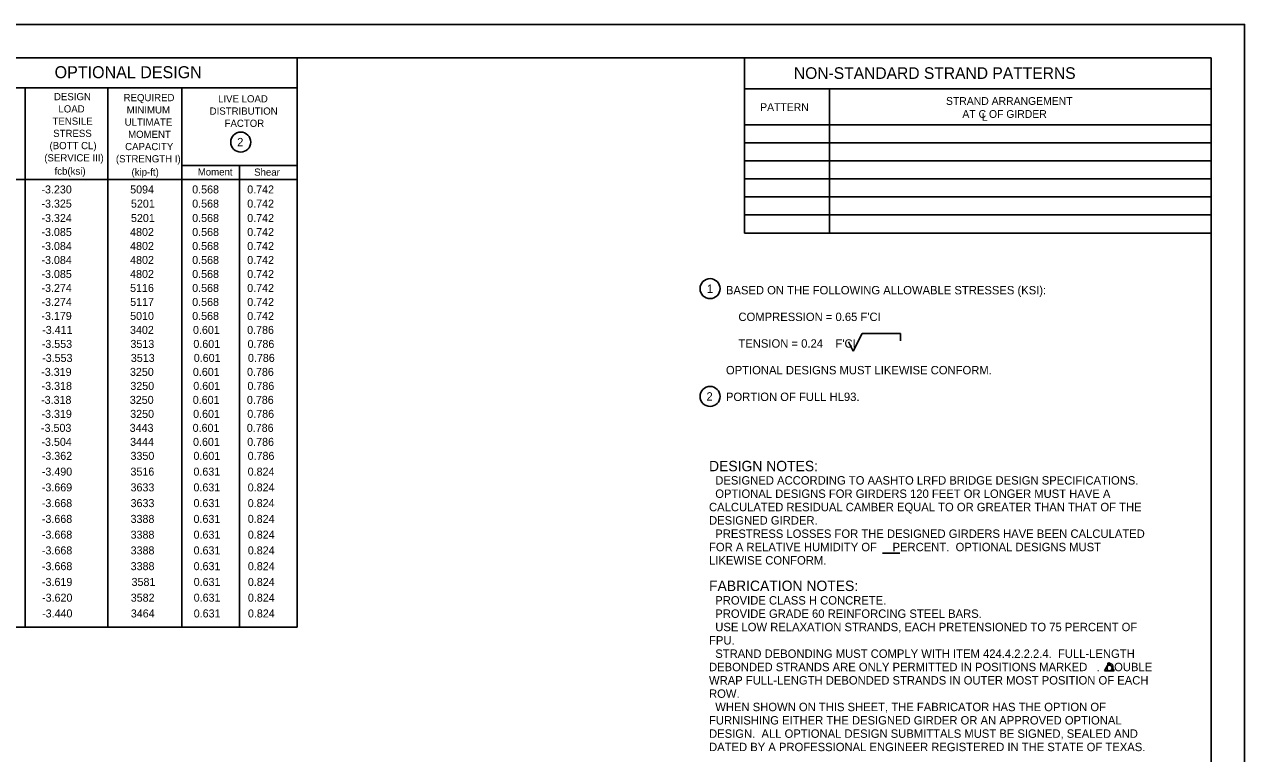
# Model space of a CAD drawing. Extents: x 998.6 to 1033.3, y 1000 to 1011.
# Drawn here: x 1007.85 to 1017, y 1005.53 to 1011 of the extents above; entities that cross this region are included whole.
import ezdxf

# ---------------------------------------------------------------- set-up
doc = ezdxf.new("R2010")
doc.units = 0
for name, color, linetype in [('D_BATCH_PLOT', 7, 'Continuous'), ('D_SHEET', 7, 'Continuous'), ('Working Level 1', 7, 'Continuous')]:
    doc.layers.add(name, color=color, linetype=linetype)

msp = doc.modelspace()

# ---------------------------------------------------------------- linework, layer by layer
at = {"layer": 'D_BATCH_PLOT'}
msp.add_lwpolyline([(1000, 1000), (1017, 1000), (1017, 1011), (1000, 1011)], close=True, dxfattribs=at)
at = {"layer": 'D_SHEET'}
for p, q in [((1000, 1011), (1017, 1011)), ((1017, 1000), (1017, 1011)), ((1001, 1010.75), (1016.75, 1010.75)), ((1016.75, 1000.25), (1016.75, 1010.75))]:
    msp.add_line(p, q, dxfattribs=at)
at = {"layer": 'Working Level 1'}
for p, q in [((1009.8951, 1010.75), (1009.8951, 1006.477)), ((1013.25, 1009.4346), (1013.25, 1010.75)), ((1013.25, 1010.75), (1016.75, 1010.75)), ((1016.75, 1009.4346), (1016.75, 1010.75)), ((1007.2976, 1010.5232), (1009.8951, 1010.5232)), ((1007.8546, 1010.5232), (1007.8546, 1006.477)), ((1008.4741, 1010.5232), (1008.4741, 1006.477)), ((1009.0311, 1010.5232), (1009.0311, 1006.477)), ((1013.25, 1010.5171), (1016.75, 1010.5171)), ((1013.8867, 1009.4346), (1013.8867, 1010.5166)), ((1013.25, 1010.2466), (1016.75, 1010.2466)), ((1013.25, 1010.1116), (1016.75, 1010.1116)), ((1009.0311, 1009.9417), (1009.8951, 1009.9417)), ((1009.4631, 1009.9417), (1009.4631, 1006.477)), ((1013.25, 1009.9762), (1016.75, 1009.9762)), ((1007.2976, 1009.8354), (1009.8951, 1009.8354)), ((1013.25, 1009.8408), (1016.75, 1009.8408)), ((1013.25, 1009.7054), (1016.75, 1009.7054)), ((1013.25, 1009.57), (1016.75, 1009.57)), ((1013.25, 1009.4346), (1016.75, 1009.4346)), ((1014.0652, 1008.5479), (1014.1325, 1008.6804)), ((1014.1325, 1008.6804), (1014.419, 1008.6804)), ((1014.419, 1008.626), (1014.419, 1008.6804)), ((1014.0299, 1008.6184), (1014.0652, 1008.5479)), ((1014.2851, 1007.0327), (1014.4142, 1007.0327)), ((1001, 1006.477), (1009.8951, 1006.477)), ((1015.9854, 1006.213), (1015.9493, 1006.1505)), ((1016.0215, 1006.1505), (1015.9854, 1006.213)), ((1015.9493, 1006.1505), (1016.0215, 1006.1505))]:
    msp.add_line(p, q, dxfattribs=at)
for centre, radius in [((1009.4717, 1010.1168), 0.075), ((1012.9913, 1009.0173), 0.075), ((1012.9913, 1008.2086), 0.075), ((1015.9854, 1006.1713), 0.0208)]:
    msp.add_circle(centre, radius, dxfattribs=at)

# ---------------------------------------------------------------- texts
for s, height, p in [('OPTIONAL DESIGN', 0.09, (1008.0761, 1010.5964)), ('NON-STANDARD STRAND PATTERNS', 0.0875, (1013.62, 1010.5909)), ('DESIGN', 0.054, (1008.0714, 1010.431)), ('REQUIRED', 0.054, (1008.5934, 1010.4237)), ('LIVE LOAD', 0.054, (1009.3018, 1010.4147)), ('PATTERN', 0.05833, (1013.3673, 1010.35)), ('STRAND ARRANGEMENT', 0.058332, (1014.7608, 1010.3962)), ('LOAD', 0.054, (1008.1045, 1010.3392)), ('MINIMUM', 0.054, (1008.6166, 1010.3319)), ('DISTRIBUTION', 0.054, (1009.239, 1010.3229)), ('AT C OF GIRDER', 0.058332, (1014.8837, 1010.2987)), ('L', 0.0583, (1015.0294, 1010.2769)), ('TENSILE', 0.054, (1008.0603, 1010.2474)), ('ULTIMATE', 0.054, (1008.6013, 1010.2401)), ('FACTOR', 0.054, (1009.3507, 1010.2311)), ('STRESS', 0.054, (1008.0654, 1010.1556)), ('MOMENT', 0.054, (1008.627, 1010.1483)), ('2', 0.063, (1009.4447, 1010.0852)), ('(BOTT CL)', 0.054, (1008.0378, 1010.0638)), ('CAPACITY', 0.054, (1008.6049, 1010.0565)), ('(SERVICE III)', 0.054, (1007.9987, 1009.972)), ('(STRENGTH I)', 0.054, (1008.5357, 1009.9647)), ('fcb(ksi)', 0.054, (1008.0758, 1009.8723)), ('(kip-ft)', 0.054, (1008.6527, 1009.8651)), ('Moment', 0.054, (1009.1495, 1009.8663)), ('Shear', 0.054, (1009.5724, 1009.8646)), ('-3.230', 0.06, (1007.9773, 1009.7317)), ('5094', 0.06, (1008.6427, 1009.7317)), ('0.568', 0.06, (1009.1079, 1009.7317)), ('0.742', 0.06, (1009.5206, 1009.7317)), ('-3.325', 0.06, (1007.9773, 1009.6254)), ('5201', 0.06, (1008.6488, 1009.6254)), ('0.568', 0.06, (1009.1079, 1009.6254)), ('0.742', 0.06, (1009.5206, 1009.6254)), ('-3.324', 0.06, (1007.9775, 1009.5174)), ('5201', 0.06, (1008.6488, 1009.5174)), ('0.568', 0.06, (1009.1079, 1009.5174)), ('0.742', 0.06, (1009.5206, 1009.5174)), ('-3.085', 0.06, (1007.9773, 1009.4124)), ('4802', 0.06, (1008.6422, 1009.4124)), ('0.568', 0.06, (1009.1079, 1009.4124)), ('0.742', 0.06, (1009.5206, 1009.4124)), ('-3.084', 0.06, (1007.9775, 1009.3075)), ('-3.084', 0.06, (1007.9775, 1009.3075)), ('4802', 0.06, (1008.6422, 1009.3075)), ('4802', 0.06, (1008.6422, 1009.3075)), ('0.568', 0.06, (1009.1079, 1009.3075)), ('0.568', 0.06, (1009.1079, 1009.3075)), ('0.742', 0.06, (1009.5206, 1009.3075)), ('0.742', 0.06, (1009.5206, 1009.3075)), ('-3.084', 0.06, (1007.9775, 1009.2025)), ('4802', 0.06, (1008.6422, 1009.2025)), ('0.568', 0.06, (1009.1079, 1009.2025)), ('0.742', 0.06, (1009.5206, 1009.2025)), ('-3.085', 0.06, (1007.9773, 1009.0975)), ('4802', 0.06, (1008.6422, 1009.0975)), ('0.568', 0.06, (1009.1079, 1009.0975)), ('0.742', 0.06, (1009.5206, 1009.0975)), ('-3.274', 0.06, (1007.9775, 1008.9926)), ('5116', 0.06, (1008.6422, 1008.9926)), ('0.568', 0.06, (1009.1079, 1008.9926)), ('0.742', 0.06, (1009.5206, 1008.9926)), ('1', 0.063, (1012.9682, 1008.9857)), ('BASED ON THE FOLLOWING ALLOWABLE STRESSES (KSI):', 0.063, (1013.1105, 1008.9745)), ('-3.274', 0.06, (1007.9775, 1008.8876)), ('5117', 0.06, (1008.6427, 1008.8876)), ('0.568', 0.06, (1009.1079, 1008.8876)), ('0.742', 0.06, (1009.5206, 1008.8876)), ('-3.179', 0.06, (1007.977, 1008.7826)), ('5010', 0.06, (1008.6424, 1008.7826)), ('0.568', 0.06, (1009.1079, 1008.7826)), ('0.742', 0.06, (1009.5206, 1008.7826)), ("    COMPRESSION = 0.65 F'CI", 0.063, (1013.1105, 1008.7745)), ('-3.411', 0.06, (1007.9829, 1008.6777)), ('3402', 0.06, (1008.6415, 1008.6777)), ('0.601', 0.06, (1009.1137, 1008.6777)), ('0.786', 0.06, (1009.5199, 1008.6777)), ('-3.553', 0.06, (1007.9796, 1008.5727)), ('3513', 0.06, (1008.6447, 1008.5727)), ('0.601', 0.06, (1009.1167, 1008.5727)), ('0.786', 0.06, (1009.5229, 1008.5727)), ("    TENSION = 0.24    F'CI", 0.063, (1013.1105, 1008.5745)), ('-3.553', 0.06, (1007.9826, 1008.4677)), ('3513', 0.06, (1008.6477, 1008.4677)), ('0.601', 0.06, (1009.1197, 1008.4677)), ('0.786', 0.06, (1009.5259, 1008.4677)), ('-3.319', 0.06, (1007.9757, 1008.3628)), ('3250', 0.06, (1008.6411, 1008.3628)), ('0.601', 0.06, (1009.1131, 1008.3628)), ('0.786', 0.06, (1009.5192, 1008.3628)), ('OPTIONAL DESIGNS MUST LIKEWISE CONFORM.', 0.063, (1013.1105, 1008.3745)), ('-3.318', 0.06, (1007.9787, 1008.2578)), ('3250', 0.06, (1008.6441, 1008.2578)), ('0.601', 0.06, (1009.1161, 1008.2578)), ('0.786', 0.06, (1009.5222, 1008.2578)), ('-3.318', 0.06, (1007.9747, 1008.1528)), ('3250', 0.06, (1008.6401, 1008.1528)), ('0.601', 0.06, (1009.1121, 1008.1528)), ('0.786', 0.06, (1009.5182, 1008.1528)), ('2', 0.063, (1012.9644, 1008.1771)), ('PORTION OF FULL HL93.', 0.063, (1013.1105, 1008.1745)), ('-3.319', 0.06, (1007.9777, 1008.0479)), ('3250', 0.06, (1008.6431, 1008.0479)), ('0.601', 0.06, (1009.1151, 1008.0479)), ('0.786', 0.06, (1009.5212, 1008.0479)), ('-3.503', 0.06, (1007.9741, 1007.9429)), ('3443', 0.06, (1008.6392, 1007.9429)), ('0.601', 0.06, (1009.1112, 1007.9429)), ('0.786', 0.06, (1009.5174, 1007.9429)), ('-3.504', 0.06, (1007.9773, 1007.8379)), ('3444', 0.06, (1008.6425, 1007.8379)), ('0.601', 0.06, (1009.1142, 1007.8379)), ('0.786', 0.06, (1009.5204, 1007.8379)), ('-3.362', 0.06, (1007.9798, 1007.733)), ('3350', 0.06, (1008.6452, 1007.733)), ('0.601', 0.06, (1009.1172, 1007.733)), ('0.786', 0.06, (1009.5234, 1007.733)), ('-3.490', 0.06, (1007.9801, 1007.6147)), ('3516', 0.06, (1008.645, 1007.6147)), ('0.631', 0.06, (1009.1172, 1007.6147)), ('0.824', 0.06, (1009.5238, 1007.6147)), ('DESIGN NOTES:', 0.078, (1012.9837, 1007.6474)), ('  DESIGNED ACCORDING TO AASHTO LRFD BRIDGE DESIGN SPECIFICATIONS.', 0.063, (1012.9837, 1007.5475)), ('-3.669', 0.06, (1007.9801, 1007.4965)), ('3633', 0.06, (1008.6455, 1007.4965)), ('0.631', 0.06, (1009.1174, 1007.4965)), ('0.824', 0.06, (1009.5241, 1007.4965)), ('  OPTIONAL DESIGNS FOR GIRDERS 120 FEET OR LONGER MUST HAVE A', 0.063, (1012.9837, 1007.4475)), ('-3.668', 0.06, (1007.9803, 1007.3783)), ('3633', 0.06, (1008.6457, 1007.3783)), ('0.631', 0.06, (1009.1177, 1007.3783)), ('0.824', 0.06, (1009.5243, 1007.3783)), ('CALCULATED RESIDUAL CAMBER EQUAL TO OR GREATER THAN THAT OF THE', 0.063, (1012.9837, 1007.3475)), ('-3.668', 0.06, (1007.9805, 1007.26)), ('3388', 0.06, (1008.6457, 1007.26)), ('0.631', 0.06, (1009.1179, 1007.26)), ('0.824', 0.06, (1009.5245, 1007.26)), ('DESIGNED GIRDER.', 0.063, (1012.9837, 1007.2475)), ('-3.668', 0.06, (1007.9808, 1007.1418)), ('3388', 0.06, (1008.6459, 1007.1418)), ('0.631', 0.06, (1009.1182, 1007.1418)), ('0.824', 0.06, (1009.5248, 1007.1418)), ('  PRESTRESS LOSSES FOR THE DESIGNED GIRDERS HAVE BEEN CALCULATED', 0.063, (1012.9837, 1007.1475)), ('FOR A RELATIVE HUMIDITY OF     PERCENT.  OPTIONAL DESIGNS MUST', 0.063, (1012.9837, 1007.0475)), ('-3.668', 0.06, (1007.981, 1007.0236)), ('3388', 0.06, (1008.6462, 1007.0236)), ('0.631', 0.06, (1009.1184, 1007.0236)), ('0.824', 0.06, (1009.525, 1007.0236)), ('-3.668', 0.06, (1007.9812, 1006.9053)), ('3388', 0.06, (1008.6464, 1006.9053)), ('0.631', 0.06, (1009.1186, 1006.9053)), ('0.824', 0.06, (1009.5252, 1006.9053)), ('LIKEWISE CONFORM.', 0.063, (1012.9837, 1006.9475)), ('-3.619', 0.06, (1007.9815, 1006.7871)), ('3581', 0.06, (1008.6532, 1006.7871)), ('0.631', 0.06, (1009.1189, 1006.7871)), ('0.824', 0.06, (1009.5255, 1006.7871)), ('FABRICATION NOTES:', 0.078, (1012.9837, 1006.7488)), ('-3.620', 0.06, (1007.9819, 1006.6689)), ('3582', 0.06, (1008.6469, 1006.6689)), ('0.631', 0.06, (1009.1191, 1006.6689)), ('0.824', 0.06, (1009.5257, 1006.6689)), ('  PROVIDE CLASS H CONCRETE.', 0.063, (1012.9837, 1006.6475)), ('-3.440', 0.06, (1007.9822, 1006.5506)), ('3464', 0.06, (1008.6476, 1006.5506)), ('0.631', 0.06, (1009.1193, 1006.5506)), ('0.824', 0.06, (1009.5259, 1006.5506)), ('  PROVIDE GRADE 60 REINFORCING STEEL BARS.', 0.063, (1012.9837, 1006.5475)), ('  USE LOW RELAXATION STRANDS, EACH PRETENSIONED TO 75 PERCENT OF', 0.063, (1012.9837, 1006.4475)), ('FPU.', 0.063, (1012.9837, 1006.3475)), ('  STRAND DEBONDING MUST COMPLY WITH ITEM 424.4.2.2.2.4.  FULL-LENGTH', 0.063, (1012.9837, 1006.2475)), ('DEBONDED STRANDS ARE ONLY PERMITTED IN POSITIONS MARKED   .  DOUBLE', 0.063, (1012.9837, 1006.1475)), ('WRAP FULL-LENGTH DEBONDED STRANDS IN OUTER MOST POSITION OF EACH', 0.063, (1012.9837, 1006.0475)), ('ROW.', 0.063, (1012.9837, 1005.9475)), ('  WHEN SHOWN ON THIS SHEET, THE FABRICATOR HAS THE OPTION OF', 0.063, (1012.9837, 1005.8475)), ('FURNISHING EITHER THE DESIGNED GIRDER OR AN APPROVED OPTIONAL', 0.063, (1012.9837, 1005.7475)), ('DESIGN.  ALL OPTIONAL DESIGN SUBMITTALS MUST BE SIGNED, SEALED AND', 0.063, (1012.9837, 1005.6475)), ('DATED BY A PROFESSIONAL ENGINEER REGISTERED IN THE STATE OF TEXAS.', 0.063, (1012.9837, 1005.5475))]:
    msp.add_text(s, height=height, dxfattribs=at).set_placement(p)

doc.saveas('drawing.dxf')
